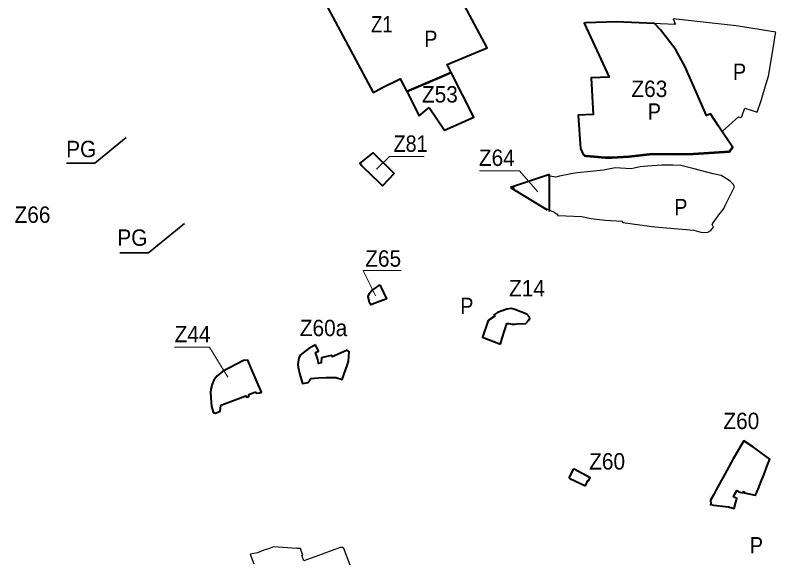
# Model space of a CAD drawing. Extents: x -650276 to -642489, y -1074311 to -1066658.
# Drawn here: x -647867 to -646754, y -1070690 to -1069891 of the extents above; entities that cross this region are included whole.
import ezdxf

# ---------------------------------------------------------------- set-up
doc = ezdxf.new("R2010")
doc.units = 0
doc.header["$LTSCALE"] = 9.6
for name, color, linetype, lineweight in [('42', 7, 'Continuous', 25), ('44', 7, 'Continuous', 40), ('45', 7, 'Continuous', 40), ('46', 7, 'Continuous', 13), ('60', 7, 'Continuous', 35)]:
    doc.layers.add(name, color=color, linetype=linetype, lineweight=lineweight)

msp = doc.modelspace()

# ---------------------------------------------------------------- linework, layer by layer
at = {"layer": '42'}
for points in [[(-646901.388, -1069904.174), (-646987.56, -1069900.52), (-647032.16, -1069902.13), (-647033.853, -1069902.188)], [(-646753.995, -1069915.425), (-646811.935, -1069906.155), (-646904.446, -1069895.991), (-646901.388, -1069902.723), (-646902.06, -1069902.694), (-646901.388, -1069904.174)], [(-647033.853, -1069902.188), (-646998.06, -1069980.039), (-646998.716, -1069980.064)], [(-646831.912, -1070060.406), (-646808.49, -1070039.689), (-646805.65, -1070040.439), (-646803.87, -1070038.879), (-646803.43, -1070037.629), (-646801.84, -1070033.139), (-646799.45, -1070026.749), (-646790.27, -1070029.749), (-646781.39, -1070032.779), (-646774.86, -1070014.019), (-646772.96, -1070007.579), (-646768.91, -1069993.979), (-646764.81, -1069980.189), (-646757.45, -1069936.669), (-646754.36, -1069917.669), (-646753.995, -1069915.425)], [(-646998.716, -1069980.064), (-646998.06, -1069981.49), (-647023.975, -1069982.477)], [(-647023.975, -1069982.477), (-647021.27, -1070034.829), (-647021.345, -1070034.832)], [(-647021.345, -1070034.832), (-647021.27, -1070036.28), (-647043.157, -1070037.286)], [(-647043.157, -1070037.286), (-647040.12, -1070084.659), (-647036.03, -1070093.509), (-647034.17, -1070095.039), (-647031.73, -1070095.759), (-647003.49, -1070098.209), (-646993.92, -1070098.039), (-646968.89, -1070096.569), (-646934.63, -1070092.789), (-646904.97, -1070093.069)], [(-646904.97, -1070093.069), (-646874.9, -1070092.649), (-646859.29, -1070091.649), (-646821.89, -1070089.249), (-646817.427, -1070083.656), (-646831.912, -1070061.857), (-646831.305, -1070061.32), (-646831.912, -1070060.406)], [(-647377.04, -1070696.22), (-647386.39, -1070671.74), (-647388.31, -1070669.95), (-647391.74, -1070670.16), (-647418.28, -1070679.89), (-647444.78, -1070689.6), (-647447.31, -1070682.72), (-647447.76, -1070681.5), (-647446.22, -1070680.91), (-647447.58, -1070677.36), (-647449.69, -1070671.81), (-647455.17, -1070671.48), (-647489.21, -1070669.41), (-647496.64, -1070671.93), (-647503.3, -1070674.3), (-647512.51, -1070677.98), (-647523.27, -1070680.11), (-647518.19, -1070693.93)]]:
    msp.add_lwpolyline(points, dxfattribs=at)
msp.add_lwpolyline([(-646874.04, -1070205.5), (-646863.66, -1070208.37), (-646859.54, -1070209.09), (-646853.67, -1070208.44), (-646849.15, -1070205.9), (-646845.3, -1070201.3), (-646847.17, -1070197.38), (-646845.76, -1070194.67), (-646836.06, -1070181.31), (-646832.62, -1070177.08), (-646829.87, -1070173.61), (-646827.95, -1070169.52), (-646820.51, -1070153.68), (-646814.53, -1070141.96), (-646816.06, -1070138.5), (-646820.35, -1070134.43), (-646825.4, -1070130.78), (-646834.04, -1070125.34), (-646845.78, -1070122.84), (-646873.5, -1070115.8), (-646892.87, -1070110.82), (-646904.66, -1070110.24), (-646920.68, -1070110.58), (-646941.99, -1070111.74), (-646952.66, -1070112.57), (-646965.6, -1070115.74), (-646989.24, -1070114.17), (-646989.24, -1070114.17), (-647005.97, -1070117.89), (-647044.19, -1070121.78), (-647051.14, -1070122.49), (-647070.7, -1070126.64), (-647075.81, -1070127.72), (-647090.2, -1070125.64), (-647133.96, -1070140.44), (-647136.65, -1070141.75), (-647137.99, -1070143.09), (-647137.96, -1070144.66), (-647136.09, -1070146.97), (-647132.95, -1070149.08), (-647097.63, -1070170.37), (-647077.39, -1070179.57), (-647076.83, -1070180.73), (-647075.42, -1070181.53), (-647073.42, -1070181.47), (-647073.35, -1070184.01), (-647061.2, -1070184.6), (-647038.31, -1070185.73), (-647024.2, -1070188.68), (-647003.89, -1070190.89), (-646978.73, -1070192.54), (-646978.72, -1070193.6), (-646977.7, -1070193.62), (-646977.7, -1070194.45), (-646938.98, -1070199.89), (-646931.25, -1070200.56)], close=True, dxfattribs=at)
at = {"layer": '44'}
msp.add_lwpolyline([(-647312.485, -1070122.583), (-647329.932, -1070140.465), (-647334.81, -1070135.73), (-647357.4, -1070113.69), (-647359.8, -1070111.34), (-647362.87, -1070107.74), (-647343.454, -1070092.368)], close=True, dxfattribs=at)
at = {"layer": '44', "lineweight": 13}
msp.add_lwpolyline([(-647268.839, -1070097.432), (-647319.538, -1070097.432), (-647338.315, -1070116.223)], dxfattribs=at)
msp.add_lwpolyline([(-647268.839, -1070097.432), (-647319.538, -1070097.432), (-647338.315, -1070116.223)], dxfattribs=at)
at = {"layer": '45'}
for p, q in [((-647085.131, -1070123.926), (-647142.227, -1070143.236)), ((-647085.131, -1070123.926), (-647142.227, -1070143.236)), ((-647085.131, -1070177.975), (-647085.131, -1070123.926)), ((-647085.131, -1070177.975), (-647085.131, -1070123.926))]:
    msp.add_line(p, q, dxfattribs=at)
for points in [[(-647365.866, -1069857.774), (-647413.461, -1069872.442), (-647343.28, -1070003.81), (-647339.69, -1070001.95), (-647330.5, -1069997.19), (-647304.05, -1069983.79), (-647294.257, -1070002.745), (-647242.254, -1069980.33), (-647229.096, -1069974.658), (-647235, -1069963), (-647176.499, -1069938.333), (-647205.781, -1069883.796), (-647217.177, -1069862.57), (-647243.231, -1069860.34), (-647278.525, -1069857.002), (-647323.794, -1069855.468)], [(-647365.866, -1069857.774), (-647413.461, -1069872.442), (-647343.28, -1070003.81), (-647339.69, -1070001.95), (-647330.5, -1069997.19), (-647304.05, -1069983.79), (-647294.257, -1070002.745), (-647242.254, -1069980.33), (-647229.096, -1069974.658), (-647235, -1069963), (-647176.499, -1069938.333), (-647205.781, -1069883.796), (-647217.177, -1069862.57), (-647243.231, -1069860.34), (-647278.525, -1069857.002), (-647323.794, -1069855.468)], [(-647032.16, -1069902.13), (-647034.51, -1069902.21), (-646998.06, -1069981.49), (-647024.05, -1069982.48), (-647021.27, -1070036.28), (-647043.25, -1070037.29), (-647040.12, -1070086.11), (-647036.03, -1070094.96), (-647034.17, -1070096.49), (-647031.73, -1070097.21), (-647003.49, -1070099.66), (-646993.92, -1070099.49), (-646968.89, -1070098.02), (-646934.63, -1070094.24), (-646904.97, -1070094.52), (-646874.9, -1070094.1), (-646859.29, -1070093.1), (-646821.89, -1070090.7), (-646817.15, -1070084.76), (-646816.9, -1070084.45), (-646837.65, -1070053.22), (-646849.79, -1070035.17), (-646855.62, -1070037.66), (-646886.85, -1069966.26), (-646900.26, -1069941.64), (-646904.72, -1069935.84), (-646922.79, -1069912.31), (-646931.67, -1069902.89), (-646987.56, -1069900.52)], [(-647261.27, -1070026.12), (-647238.99, -1070059.05), (-647195.933, -1070040.107), (-647229.096, -1069974.658), (-647294.257, -1070002.745), (-647276, -1070038.08)], [(-647261.27, -1070026.12), (-647238.99, -1070059.05), (-647195.933, -1070040.107), (-647229.096, -1069974.658), (-647294.257, -1070002.745), (-647276, -1070038.08)], [(-647333.87, -1070285.66), (-647324.11, -1070306.21), (-647324.94, -1070306.63), (-647327.18, -1070307.52), (-647333.97, -1070310.22), (-647346.97, -1070315.05), (-647349, -1070312), (-647350.67, -1070302.55), (-647348.677, -1070297.894), (-647345.27, -1070293.99), (-647343.9, -1070292.96), (-647337.56, -1070288.43), (-647334.91, -1070286.51)], [(-647333.87, -1070285.66), (-647324.11, -1070306.21), (-647324.94, -1070306.63), (-647327.18, -1070307.52), (-647333.97, -1070310.22), (-647346.97, -1070315.05), (-647349, -1070312), (-647350.67, -1070302.55), (-647348.677, -1070297.894), (-647345.27, -1070293.99), (-647343.9, -1070292.96), (-647337.56, -1070288.43), (-647334.91, -1070286.51)], [(-647427.8, -1070373.32), (-647437.76, -1070378.66), (-647449.69, -1070387.83), (-647452.17, -1070392.38), (-647453.71, -1070401.81), (-647453.35, -1070406.09), (-647450.51, -1070416.96), (-647446.93, -1070429.99), (-647438.45, -1070428.47), (-647434.85, -1070422.64), (-647423.38, -1070421.87), (-647412.51, -1070421.5), (-647400.41, -1070421.08), (-647398.21, -1070421.15), (-647388.6, -1070424.24), (-647381.11, -1070402.45), (-647379.3, -1070397.57), (-647378.49, -1070383.91), (-647381.65, -1070381.45), (-647400.22, -1070389.64), (-647403.27, -1070390.91), (-647404, -1070388.84), (-647409.36, -1070390.24), (-647419.08, -1070392.52), (-647419.68, -1070399.59), (-647423.58, -1070400.59), (-647424.54, -1070394.78), (-647425.99, -1070390.47), (-647427.96, -1070384.64), (-647423.57, -1070382.64)], [(-647427.8, -1070373.32), (-647437.76, -1070378.66), (-647449.69, -1070387.83), (-647452.17, -1070392.38), (-647453.71, -1070401.81), (-647453.35, -1070406.09), (-647450.51, -1070416.96), (-647446.93, -1070429.99), (-647438.45, -1070428.47), (-647434.85, -1070422.64), (-647423.38, -1070421.87), (-647412.51, -1070421.5), (-647400.41, -1070421.08), (-647398.21, -1070421.15), (-647388.6, -1070424.24), (-647381.11, -1070402.45), (-647379.3, -1070397.57), (-647378.49, -1070383.91), (-647381.65, -1070381.45), (-647400.22, -1070389.64), (-647403.27, -1070390.91), (-647404, -1070388.84), (-647409.36, -1070390.24), (-647419.08, -1070392.52), (-647419.68, -1070399.59), (-647423.58, -1070400.59), (-647424.54, -1070394.78), (-647425.99, -1070390.47), (-647427.96, -1070384.64), (-647423.57, -1070382.64)], [(-647515.73, -1070442.32), (-647514.23, -1070444.18), (-647509.22, -1070443.62), (-647506.95, -1070442.71), (-647522.54, -1070406.51), (-647527.1, -1070395.72), (-647533.1, -1070396.26), (-647564.01, -1070412.59), (-647572.37, -1070419.41), (-647576.48, -1070425.09), (-647579.22, -1070431.05), (-647581.04, -1070438.4), (-647581.54, -1070443.7), (-647580.1, -1070463.69), (-647576.92, -1070473), (-647574.28, -1070473.46), (-647567.32, -1070470.66), (-647566.55, -1070462.22), (-647565.11, -1070461.12), (-647529.74, -1070448.27), (-647528.28, -1070449.87), (-647525.54, -1070448.89), (-647525.45, -1070446.21)], [(-647515.73, -1070442.32), (-647514.23, -1070444.18), (-647509.22, -1070443.62), (-647506.95, -1070442.71), (-647522.54, -1070406.51), (-647527.1, -1070395.72), (-647533.1, -1070396.26), (-647564.01, -1070412.59), (-647572.37, -1070419.41), (-647576.48, -1070425.09), (-647579.22, -1070431.05), (-647581.04, -1070438.4), (-647581.54, -1070443.7), (-647580.1, -1070463.69), (-647576.92, -1070473), (-647574.28, -1070473.46), (-647567.32, -1070470.66), (-647566.55, -1070462.22), (-647565.11, -1070461.12), (-647529.74, -1070448.27), (-647528.28, -1070449.87), (-647525.54, -1070448.89), (-647525.45, -1070446.21)], [(-646802.19, -1070516.26), (-646816.42, -1070540.49), (-646828.45, -1070562.89), (-646841.16, -1070585.79), (-646844.76, -1070592.54), (-646849.72, -1070600.98), (-646848.99, -1070606.28), (-646849.59, -1070607.4), (-646844.96, -1070607.98), (-646827.88, -1070610.12), (-646822.99, -1070610.51), (-646815.05, -1070613.14), (-646812.5, -1070603.78), (-646811.5, -1070600.29), (-646810.82, -1070598.23), (-646816.11, -1070595.8), (-646814.52, -1070592.78), (-646811.06, -1070586.67), (-646806.41, -1070589), (-646802.06, -1070589.93), (-646801.73, -1070588.37), (-646800.13, -1070588.71), (-646800.47, -1070590.28), (-646784.18, -1070593.76), (-646784, -1070593.34), (-646783.59, -1070593.52), (-646779.9, -1070584.92), (-646774.91, -1070571.88), (-646771.17, -1070562.7), (-646767.63, -1070553.09), (-646762.71, -1070540.85), (-646782.63, -1070526.02), (-646788, -1070522.49), (-646800.94, -1070514.04)], [(-646802.19, -1070516.26), (-646816.42, -1070540.49), (-646828.45, -1070562.89), (-646841.16, -1070585.79), (-646844.76, -1070592.54), (-646849.72, -1070600.98), (-646848.99, -1070606.28), (-646849.59, -1070607.4), (-646844.96, -1070607.98), (-646827.88, -1070610.12), (-646822.99, -1070610.51), (-646815.05, -1070613.14), (-646812.5, -1070603.78), (-646811.5, -1070600.29), (-646810.82, -1070598.23), (-646816.11, -1070595.8), (-646814.52, -1070592.78), (-646811.06, -1070586.67), (-646806.41, -1070589), (-646802.06, -1070589.93), (-646801.73, -1070588.37), (-646800.13, -1070588.71), (-646800.47, -1070590.28), (-646784.18, -1070593.76), (-646784, -1070593.34), (-646783.59, -1070593.52), (-646779.9, -1070584.92), (-646774.91, -1070571.88), (-646771.17, -1070562.7), (-646767.63, -1070553.09), (-646762.71, -1070540.85), (-646782.63, -1070526.02), (-646788, -1070522.49), (-646800.94, -1070514.04)], [(-647032.738, -1070579.83), (-647029.168, -1070572.13), (-647028.248, -1070572.63), (-647025.868, -1070568.26), (-647049.248, -1070555.64), (-647050.098, -1070555.74), (-647050.868, -1070556.59), (-647052.498, -1070559.7), (-647056.518, -1070567.41), (-647056.528, -1070568.32), (-647055.518, -1070569.07)]]:
    msp.add_lwpolyline(points, close=True, dxfattribs=at)
for points in [[(-647142.227, -1070143.236), (-647097.63, -1070170.37), (-647088.916, -1070175.672)], [(-647142.227, -1070143.236), (-647097.63, -1070170.37), (-647088.916, -1070175.672)], [(-647113.37, -1070333.96), (-647118.28, -1070328.29), (-647135.94, -1070321.54), (-647140.83, -1070320.47), (-647147.66, -1070321.04), (-647161.17, -1070326.29), (-647167.03, -1070329.81)], [(-647167.03, -1070329.81), (-647165.36, -1070331.59), (-647174.81, -1070338.01), (-647183.55, -1070362.35), (-647156.9, -1070372.69)], [(-647132.49, -1070342.91), (-647119.88, -1070342.1), (-647116.03, -1070337.68), (-647113.37, -1070333.96)], [(-647156.9, -1070372.69), (-647154.31, -1070363.46), (-647151.09, -1070353.15), (-647147.6, -1070341.95), (-647144.57, -1070342.42), (-647139.84, -1070343.16), (-647135.62, -1070343.32), (-647132.49, -1070342.91)]]:
    msp.add_lwpolyline(points, dxfattribs=at)
at = {"layer": '46'}
for points in [[(-647187.627, -1070118.571), (-647128.949, -1070118.571), (-647102.191, -1070149.577)], [(-647187.627, -1070118.571), (-647128.949, -1070118.571), (-647102.191, -1070149.577)], [(-647302.639, -1070264.673), (-647358.031, -1070264.673), (-647340.193, -1070301.786)], [(-647302.639, -1070264.673), (-647358.031, -1070264.673), (-647340.193, -1070301.786)], [(-647634.056, -1070376.951), (-647582.888, -1070376.951), (-647556.111, -1070420.553)], [(-647634.056, -1070376.951), (-647582.888, -1070376.951), (-647556.111, -1070420.553)]]:
    msp.add_lwpolyline(points, dxfattribs=at)
at = {"layer": '60'}
for points in [[(-647792.254, -1070107.298), (-647750.945, -1070107.298), (-647704.94, -1070069.715)], [(-647792.254, -1070107.298), (-647750.945, -1070107.298), (-647704.94, -1070069.715)], [(-647714.329, -1070238.836), (-647672.08, -1070238.836), (-647619.504, -1070195.616)], [(-647714.329, -1070238.836), (-647672.08, -1070238.836), (-647619.504, -1070195.616)]]:
    msp.add_lwpolyline(points, dxfattribs=at)

# ---------------------------------------------------------------- texts
at = {"layer": '44', "width": 0.9}
msp.add_text('Z81', height=24, dxfattribs=at).set_placement((-647313.531, -1070090.851))
msp.add_text('Z81', height=24, dxfattribs=at).set_placement((-647313.531, -1070090.851))
at = {"layer": '46'}
for s, width, p in [('Z1', 0.85, (-647346.649, -1069916.072)), ('Z1', 0.85, (-647346.649, -1069916.072)), ('Z63', 0.95, (-646965.327, -1070010.57)), ('Z53', 0.95, (-647272.017, -1070018.639)), ('Z53', 0.95, (-647272.017, -1070018.639)), ('Z64', 0.95, (-647188.663, -1070111.521)), ('Z64', 0.95, (-647188.663, -1070111.521)), ('Z66', 0.95, (-647868.376, -1070194.801)), ('Z65', 0.95, (-647355.018, -1070259.014)), ('Z65', 0.95, (-647355.018, -1070259.014)), ('Z14', 0.95, (-647144.477, -1070302.522)), ('Z44', 0.95, (-647634.087, -1070369.724)), ('Z44', 0.95, (-647634.087, -1070369.724)), ('Z60a', 0.95, (-647450.804, -1070360.702)), ('Z60', 0.95, (-646830.725, -1070496.795)), ('Z60', 0.95, (-647027.184, -1070556.06))]:
    msp.add_text(s, height=24, dxfattribs=dict(at, width=width)).set_placement(p)
at = {"layer": '60'}
for s, width, p in [('P', 0.9, (-647268.59, -1069937.47)), ('P', 0.9, (-647268.59, -1069937.47)), ('P', 0.9, (-646816.629, -1069985.717)), ('P', 0.9, (-646816.629, -1069985.717)), ('P', 0.9, (-646941.403, -1070043.945)), ('P', 0.9, (-646941.403, -1070043.945)), ('PG', 0.95, (-647792.805, -1070098.685)), ('PG', 0.95, (-647792.805, -1070098.685)), ('P', 0.9, (-646902.585, -1070183.692)), ('P', 0.9, (-646902.585, -1070183.692)), ('PG', 0.95, (-647717.94, -1070228.451)), ('PG', 0.95, (-647717.94, -1070228.451)), ('P', 0.9, (-647215.907, -1070328.431)), ('P', 0.9, (-647215.907, -1070328.431)), ('P', 0.9, (-646791.982, -1070678.937)), ('P', 0.9, (-646791.982, -1070678.937))]:
    msp.add_text(s, height=24, dxfattribs=dict(at, width=width)).set_placement(p)

doc.saveas('drawing.dxf')
